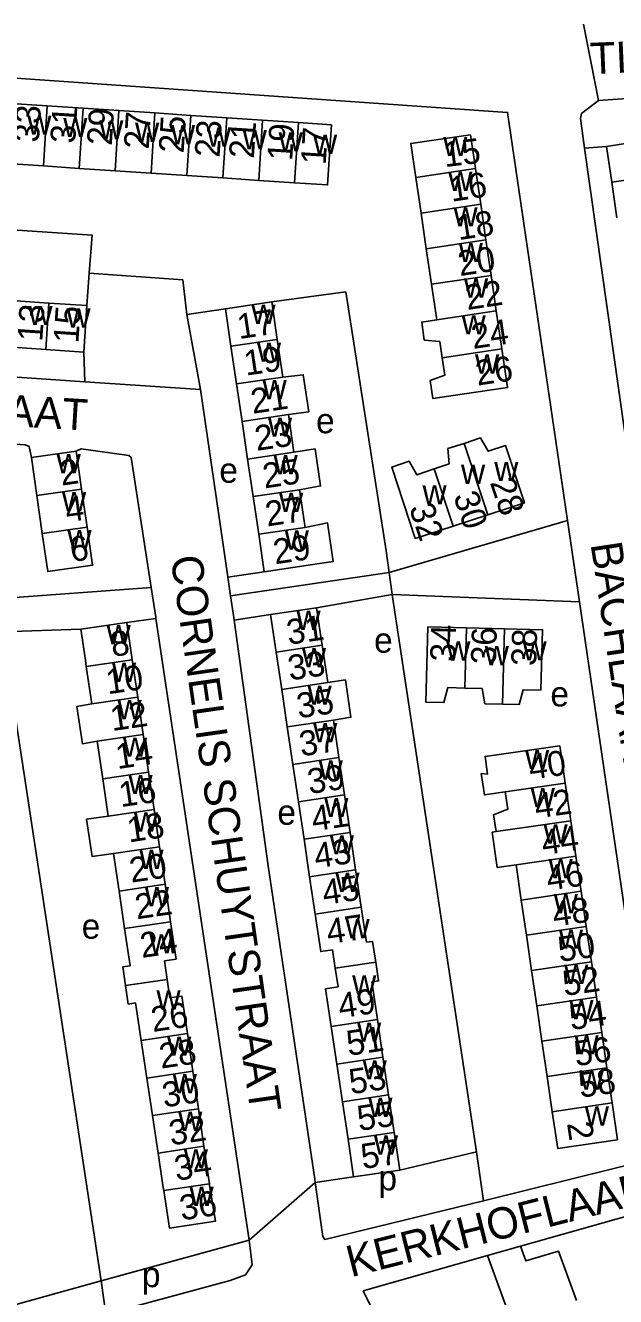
# Model space of a CAD drawing. Extents: x 159045 to 160918, y 380454 to 382516.
# Drawn here: x 159415.3 to 159509.6, y 380982.2 to 381185.5 of the extents above; entities that cross this region are included whole.
import ezdxf

# ---------------------------------------------------------------- set-up
doc = ezdxf.new("R2010")
doc.units = 0
for name, color, linetype in [('BLT_Basislijn', 7, 'Continuous'), ('BLT_Bebouwing', 7, 'Continuous'), ('BLT_Centroide', 7, 'Continuous'), ('BLT_Huisnummer', 7, 'Continuous'), ('BLT_Huisnummer_ tussenligend', 7, 'Continuous'), ('BLT_Onderverdeling_panden', 7, 'Continuous'), ('BLT_Straatnaam', 7, 'Continuous'), ('BLT_Vlakafsluiter', 7, 'Continuous')]:
    doc.layers.add(name, color=color, linetype=linetype)

msp = doc.modelspace()

# ---------------------------------------------------------------- linework, layer by layer
at = {"layer": 'BLT_Basislijn'}
for p, q in [((159504.65, 381165.85), (159508.16, 381166.12)), ((159504.65, 381165.85), (159511.98, 381113.94)), ((159424.57, 381133.23), (159424.74, 381128.49)), ((159424.74, 381128.49), (159443.24, 381127.24)), ((159501.91, 381106.29), (159473.38, 381098)), ((159501.91, 381106.29), (159503.82, 381093.29)), ((159447.6, 381097.25), (159453.42, 381098.11)), ((159447.6, 381097.25), (159448.04, 381094.26)), ((159473.38, 381098), (159448.04, 381094.26)), ((159473.88, 381094.5), (159473.38, 381098)), ((159406.83, 381093.49), (159435.36, 381095.58)), ((159461.81, 381092.35), (159473.88, 381094.5)), ((159473.88, 381094.5), (159503.82, 381093.29)), ((159448.61, 381090.35), (159454.45, 381091.26)), ((159436.12, 381090.64), (159431.45, 381090.01)), ((159451.01, 380991.23), (159436.12, 381090.64)), ((159424.11, 381088.94), (159411.57, 381088.52)), ((159411.57, 381088.52), (159427.34, 380984.74)), ((159475.09, 381002.45), (159487.38, 381005.39)), ((159487.38, 381005.39), (159488.5, 380997.53)), ((159467.71, 381001.35), (159461.58, 381000.46)), ((159494.38, 380990.27), (159515.4, 380996.22)), ((159427.34, 380984.74), (159451.01, 380991.23)), ((159489.14, 380988.79), (159494.38, 380990.27)), ((159469.22, 380983.16), (159489.14, 380988.79)), ((159493.11, 380977.83), (159489.14, 380988.79)), ((159427.34, 380984.74), (159401.24, 380977.5)), ((159428.12, 380979.39), (159427.34, 380984.74)), ((159471.52, 380978.46), (159469.22, 380983.16))]:
    msp.add_line(p, q, dxfattribs=at)
for points in [[(159372.56, 381179.9), (159492.32, 381171.55), (159501.91, 381106.29)], [(159506.86, 381173.46), (159546.37, 381176.21), (159549.81, 381173.28), (159549.76, 381169.23)], [(159504.65, 381165.85), (159504, 381170.58), (159504.16, 381171.37), (159506.86, 381173.46)], [(159425.46, 381145.86), (159425.92, 381151.93), (159383.62, 381154.73)], [(159425.07, 381140.66), (159425.46, 381145.86)], [(159441.06, 381139.22), (159440.41, 381144.8), (159425.46, 381145.86)], [(159454.64, 381141.26), (159466.45, 381142.84), (159472.9, 381101.45), (159473.38, 381098)], [(159441.06, 381139.22), (159447.22, 381140.16)], [(159443.24, 381127.24), (159441.06, 381139.22)], [(159365.96, 381132.51), (159399.9, 381130.18), (159424.74, 381128.49)], [(159443.24, 381127.24), (159447.54, 381097.66), (159447.6, 381097.25)], [(159416.22, 381116.38), (159415.86, 381118.12), (159415.22, 381118.39), (159403, 381119.22)], [(159423.38, 381117.4), (159424.16, 381117.76), (159431.78, 381116.69), (159432.16, 381116.4), (159435.36, 381095.58)], [(159435.36, 381095.58), (159436.08, 381090.87), (159436.12, 381090.64)], [(159448.04, 381094.26), (159448.55, 381090.78), (159448.61, 381090.35)], [(159473.88, 381094.5), (159487.28, 381006.08), (159487.38, 381005.39)], [(159503.82, 381093.29), (159516.85, 381004.58)], [(159461.58, 381000.46), (159461.5, 381000.99), (159454.07, 381051.07), (159448.61, 381090.35)], [(159516.85, 381004.58), (159488.5, 380997.53)], [(159461.58, 381000.46), (159462.77, 380991.85), (159463.09, 380991.37), (159488.5, 380997.53)], [(159451.01, 380991.23), (159451.52, 380987.33), (159450.46, 380985.71), (159447.97, 380984.78), (159428.12, 380979.39)], [(159494.38, 380990.27), (159495.25, 380987.93), (159500.46, 380989.49), (159503.36, 380981.6)]]:
    msp.add_lwpolyline(points, dxfattribs=at)
at = {"layer": 'BLT_Bebouwing'}
for p, q in [((159418.74, 381172.61), (159413, 381173)), ((159424.48, 381172.23), (159418.74, 381172.61)), ((159430.21, 381171.84), (159424.48, 381172.23)), ((159435.95, 381171.46), (159430.21, 381171.84)), ((159441.69, 381171.07), (159435.95, 381171.46)), ((159447.43, 381170.69), (159441.69, 381171.07)), ((159453.16, 381170.3), (159447.43, 381170.69)), ((159458.9, 381169.92), (159453.16, 381170.3)), ((159464.18, 381169.56), (159458.9, 381169.92)), ((159486.41, 381167.99), (159487.2, 381162.57)), ((159515.44, 381167.24), (159508.16, 381166.12)), ((159508.16, 381166.12), (159508.98, 381160.39)), ((159412.39, 381163.37), (159418.13, 381162.99)), ((159418.13, 381162.99), (159423.87, 381162.6)), ((159423.87, 381162.6), (159429.6, 381162.22)), ((159429.6, 381162.22), (159435.34, 381161.84)), ((159487.2, 381162.57), (159488.04, 381156.88)), ((159478.5, 381155.45), (159477.66, 381161.14)), ((159508.98, 381160.39), (159509.8, 381154.67)), ((159488.04, 381156.88), (159488.87, 381151.19)), ((159479.33, 381149.76), (159478.5, 381155.45)), ((159488.87, 381151.19), (159489.7, 381145.5)), ((159480.17, 381144.08), (159479.33, 381149.76)), ((159481, 381138.39), (159480.17, 381144.08)), ((159489.7, 381145.5), (159490.53, 381139.81)), ((159419.01, 381141.07), (159412.95, 381141.49)), ((159425.07, 381140.66), (159419.01, 381141.07)), ((159447.22, 381140.16), (159448.11, 381134.16)), ((159455.52, 381135.25), (159454.64, 381141.26)), ((159490.53, 381139.81), (159491.42, 381133.73)), ((159418.51, 381133.64), (159412.44, 381134.05)), ((159448.11, 381134.16), (159448.99, 381128.15)), ((159456.41, 381129.24), (159455.52, 381135.25)), ((159424.57, 381133.23), (159418.51, 381133.64)), ((159448.99, 381128.15), (159449.88, 381122.14)), ((159449.88, 381122.14), (159450.77, 381116.13)), ((159458.18, 381117.23), (159457.29, 381123.23)), ((159416.22, 381116.38), (159423.38, 381117.4)), ((159417.09, 381110.3), (159416.22, 381116.38)), ((159423.38, 381117.4), (159424.24, 381111.32)), ((159450.77, 381116.13), (159451.65, 381110.12)), ((159424.24, 381111.32), (159425.11, 381105.24)), ((159417.95, 381104.22), (159417.09, 381110.3)), ((159451.65, 381110.12), (159452.54, 381104.12)), ((159459.95, 381105.21), (159459.07, 381111.22)), ((159477.57, 381103.43), (159483.61, 381105.4)), ((159483.61, 381105.4), (159489.17, 381107.21)), ((159452.54, 381104.12), (159453.42, 381098.11)), ((159454.45, 381091.26), (159461.81, 381092.35)), ((159455.34, 381085.28), (159454.45, 381091.26)), ((159431.45, 381090.01), (159424.11, 381088.94)), ((159432.33, 381084.03), (159431.45, 381090.01)), ((159479.6, 381089.32), (159485.77, 381089.16)), ((159485.77, 381089.16), (159491.86, 381089)), ((159456.23, 381079.29), (159455.34, 381085.28)), ((159462.7, 381086.37), (159463.59, 381080.38)), ((159424.99, 381082.96), (159425.86, 381076.98)), ((159433.2, 381078.05), (159432.33, 381084.03)), ((159457.12, 381073.3), (159456.23, 381079.29)), ((159434.08, 381072.07), (159433.2, 381078.05)), ((159458.01, 381067.32), (159457.12, 381073.3)), ((159464.48, 381074.4), (159465.37, 381068.41)), ((159426.74, 381071), (159427.61, 381065.01)), ((159434.95, 381066.09), (159434.08, 381072.07)), ((159500.66, 381070.3), (159501.54, 381064.32)), ((159458.9, 381061.33), (159458.01, 381067.32)), ((159465.37, 381068.41), (159466.26, 381062.43)), ((159427.61, 381065.01), (159428.49, 381059.03)), ((159435.83, 381060.11), (159434.95, 381066.09)), ((159501.54, 381064.32), (159502.42, 381058.29)), ((159459.79, 381055.35), (159458.9, 381061.33)), ((159466.26, 381062.43), (159467.15, 381056.44)), ((159436.7, 381054.12), (159435.83, 381060.11)), ((159467.15, 381056.44), (159468.04, 381050.46)), ((159502.42, 381058.29), (159503.24, 381052.65)), ((159460.68, 381049.36), (159459.79, 381055.35)), ((159429.36, 381053.05), (159430.24, 381047.07)), ((159437.58, 381048.14), (159436.7, 381054.12)), ((159468.04, 381050.46), (159468.93, 381044.47)), ((159494.52, 381045.62), (159493.69, 381051.26)), ((159461.57, 381043.38), (159460.68, 381049.36)), ((159430.24, 381047.07), (159431.11, 381041.09)), ((159438.45, 381042.16), (159437.58, 381048.14)), ((159468.93, 381044.47), (159469.76, 381038.88)), ((159495.34, 381039.99), (159494.52, 381045.62)), ((159431.11, 381041.09), (159431.99, 381035.11)), ((159496.17, 381034.34), (159495.34, 381039.99)), ((159464.79, 381034.71), (159464.35, 381037.67)), ((159437.9, 381032.93), (159437.46, 381035.91)), ((159465.23, 381031.74), (159464.79, 381034.71)), ((159497, 381028.7), (159496.17, 381034.34)), ((159438.33, 381029.97), (159437.9, 381032.93)), ((159471.51, 381026.53), (159470.62, 381032.54)), ((159433.76, 381023.17), (159432.86, 381029.17)), ((159497.83, 381023.06), (159497, 381028.7)), ((159472.41, 381020.51), (159471.51, 381026.53)), ((159442.03, 381018.27), (159441.15, 381024.27)), ((159465.03, 381019.41), (159464.14, 381025.43)), ((159434.66, 381017.17), (159433.76, 381023.17)), ((159498.65, 381017.43), (159497.83, 381023.06)), ((159473.3, 381014.49), (159472.41, 381020.51)), ((159442.91, 381012.27), (159442.03, 381018.27)), ((159465.93, 381013.39), (159465.03, 381019.41)), ((159509.02, 381013.18), (159508.19, 381018.82)), ((159435.56, 381011.17), (159434.66, 381017.17)), ((159499.48, 381011.79), (159498.65, 381017.43)), ((159474.2, 381008.47), (159473.3, 381014.49)), ((159443.79, 381006.27), (159442.91, 381012.27)), ((159466.82, 381007.38), (159465.93, 381013.39)), ((159436.46, 381005.17), (159435.56, 381011.17)), ((159444.66, 381000.26), (159443.79, 381006.27)), ((159467.71, 381001.35), (159466.82, 381007.38)), ((159437.23, 381000.01), (159436.46, 381005.17)), ((159475.09, 381002.45), (159467.71, 381001.35)), ((159437.36, 380999.17), (159437.23, 381000.01)), ((159444.7, 381000), (159444.66, 381000.26))]:
    msp.add_line(p, q, dxfattribs=at)
for points in [[(159458.29, 381160.3), (159463.56, 381159.95), (159464.18, 381169.56)], [(159477.66, 381161.14), (159476.86, 381166.59), (159486.41, 381167.99)], [(159435.34, 381161.84), (159441.08, 381161.45)], [(159441.08, 381161.45), (159446.82, 381161.07)], [(159446.82, 381161.07), (159452.55, 381160.68)], [(159452.55, 381160.68), (159458.29, 381160.3)], [(159424.57, 381133.23), (159424.91, 381138.22), (159425.07, 381140.66)], [(159454.64, 381141.26), (159452.17, 381140.89), (159447.22, 381140.16)], [(159481.87, 381132.3), (159481.48, 381134.92), (159479.02, 381135.15), (159478.6, 381138.03), (159481, 381138.39)], [(159491.42, 381133.73), (159492.32, 381127.56), (159480.4, 381125.8), (159479.97, 381128.7), (159482.28, 381129.52), (159481.87, 381132.3)], [(159457.29, 381123.23), (159460.55, 381123.68), (159459.67, 381129.61), (159456.41, 381129.24)], [(159489.17, 381107.21), (159495.01, 381109.11), (159492.01, 381118.29), (159489.23, 381117.38), (159487.98, 381119.5), (159485.37, 381118.64)], [(159459.07, 381111.22), (159462.43, 381111.83), (159461.55, 381117.76), (159458.18, 381117.23)], [(159485.37, 381118.64), (159482.78, 381117.79), (159482.99, 381115.34), (159480.57, 381114.54)], [(159480.57, 381114.54), (159477.81, 381113.63), (159476.61, 381115.77), (159473.82, 381114.85), (159477.57, 381103.43)], [(159425.11, 381105.24), (159425.98, 381099.16), (159418.82, 381098.14), (159417.95, 381104.22)], [(159453.42, 381098.11), (159460.84, 381099.2), (159464.47, 381099.74), (159463.56, 381105.93), (159459.95, 381105.21)], [(159461.81, 381092.35), (159462.54, 381087.41), (159462.7, 381086.37)], [(159485.48, 381079.5), (159482.79, 381079.58), (159482.16, 381077.2), (159479.27, 381077.28), (159479.6, 381089.32)], [(159491.86, 381089), (159497.92, 381088.85), (159497.67, 381079.19), (159494.8, 381079.25), (159494.16, 381076.87), (159491.51, 381076.95)], [(159424.11, 381088.94), (159424.84, 381083.99), (159424.99, 381082.96)], [(159463.59, 381080.38), (159466.41, 381080.81), (159467.29, 381074.85), (159464.48, 381074.4)], [(159491.51, 381076.95), (159488.71, 381077.02), (159488.25, 381079.43), (159485.48, 381079.5)], [(159425.86, 381076.98), (159423.49, 381076.57), (159424.36, 381070.61), (159426.74, 381071)], [(159491.96, 381062.91), (159488.63, 381062.43), (159488.13, 381065.85), (159489.14, 381065.75), (159488.73, 381068.55), (159500.66, 381070.3)], [(159490.49, 381056.56), (159490.1, 381059.23), (159492.36, 381060.13), (159491.96, 381062.91)], [(159428.49, 381059.03), (159425.03, 381058.54), (159425.9, 381052.59), (159429.36, 381053.05)], [(159493.69, 381051.26), (159490.67, 381050.81), (159489.84, 381056.46), (159490.49, 381056.56)], [(159503.24, 381052.65), (159504.07, 381047.02)], [(159504.07, 381047.02), (159504.89, 381041.37)], [(159464.35, 381037.67), (159462.46, 381037.39), (159461.57, 381043.38)], [(159437.46, 381035.91), (159439.33, 381036.18), (159438.45, 381042.16)], [(159504.89, 381041.37), (159505.72, 381035.73)], [(159469.76, 381038.88), (159470.74, 381039.02), (159471.23, 381036.01), (159471.28, 381035.67)], [(159431.25, 381031.96), (159430.81, 381034.93), (159431.99, 381035.11)], [(159471.28, 381035.67), (159471.72, 381032.69), (159470.62, 381032.54)], [(159505.72, 381035.73), (159506.55, 381030.08)], [(159432.86, 381029.17), (159431.68, 381028.99), (159431.25, 381031.96)], [(159441.15, 381024.27), (159440.28, 381030.25), (159438.33, 381029.97)], [(159464.14, 381025.43), (159463.24, 381031.45), (159465.23, 381031.74)], [(159506.55, 381030.08), (159507.37, 381024.45)], [(159507.37, 381024.45), (159508.19, 381018.82)], [(159509.02, 381013.18), (159509.88, 381007.3), (159500.34, 381005.92), (159499.48, 381011.79)], [(159475.09, 381002.45), (159474.36, 381007.4), (159474.2, 381008.47)], [(159444.7, 381000), (159445.63, 380994.27), (159438.26, 380993.17), (159437.52, 380998.11), (159437.36, 380999.17)]]:
    msp.add_lwpolyline(points, dxfattribs=at)
at = {"layer": 'BLT_Onderverdeling_panden'}
for p, q in [((159418.13, 381162.99), (159418.74, 381172.61)), ((159423.87, 381162.6), (159424.48, 381172.23)), ((159429.6, 381162.22), (159430.21, 381171.84)), ((159435.34, 381161.84), (159435.95, 381171.46)), ((159441.08, 381161.45), (159441.69, 381171.07)), ((159446.82, 381161.07), (159447.43, 381170.69)), ((159452.55, 381160.68), (159453.16, 381170.3)), ((159458.29, 381160.3), (159458.9, 381169.92)), ((159477.66, 381161.14), (159487.2, 381162.57)), ((159508.98, 381160.39), (159516.25, 381161.43)), ((159478.5, 381155.45), (159488.04, 381156.88)), ((159479.33, 381149.76), (159488.87, 381151.19)), ((159480.17, 381144.08), (159489.7, 381145.5)), ((159418.51, 381133.64), (159419.01, 381141.07)), ((159481, 381138.39), (159490.53, 381139.81)), ((159448.11, 381134.16), (159455.52, 381135.25)), ((159481.87, 381132.3), (159491.42, 381133.73)), ((159448.99, 381128.15), (159456.41, 381129.24)), ((159449.88, 381122.14), (159457.29, 381123.23)), ((159489.17, 381107.21), (159485.37, 381118.64)), ((159450.77, 381116.13), (159458.18, 381117.23)), ((159483.61, 381105.4), (159480.57, 381114.54)), ((159424.24, 381111.32), (159417.09, 381110.3)), ((159451.65, 381110.12), (159459.07, 381111.22)), ((159425.11, 381105.24), (159417.95, 381104.22)), ((159452.54, 381104.12), (159459.95, 381105.21)), ((159485.48, 381079.5), (159485.77, 381089.16)), ((159491.51, 381076.95), (159491.86, 381089)), ((159455.34, 381085.28), (159462.7, 381086.37)), ((159432.33, 381084.03), (159424.99, 381082.96)), ((159456.23, 381079.29), (159463.59, 381080.38)), ((159433.2, 381078.05), (159425.86, 381076.98)), ((159457.12, 381073.3), (159464.48, 381074.4)), ((159434.08, 381072.07), (159426.74, 381071)), ((159458.01, 381067.32), (159465.37, 381068.41)), ((159434.95, 381066.09), (159427.61, 381065.01)), ((159491.96, 381062.91), (159501.54, 381064.32)), ((159458.9, 381061.33), (159466.26, 381062.43)), ((159435.83, 381060.11), (159428.49, 381059.03)), ((159459.79, 381055.35), (159467.15, 381056.44)), ((159490.49, 381056.56), (159502.42, 381058.29)), ((159436.7, 381054.12), (159429.36, 381053.05)), ((159493.69, 381051.26), (159503.24, 381052.65)), ((159460.68, 381049.36), (159468.04, 381050.46)), ((159437.58, 381048.14), (159430.24, 381047.07)), ((159494.52, 381045.62), (159504.07, 381047.02)), ((159461.57, 381043.38), (159468.93, 381044.47)), ((159438.45, 381042.16), (159431.11, 381041.09)), ((159495.34, 381039.99), (159504.89, 381041.37)), ((159464.79, 381034.71), (159471.28, 381035.67)), ((159496.17, 381034.34), (159505.72, 381035.73)), ((159431.25, 381031.96), (159437.9, 381032.93)), ((159497, 381028.7), (159506.55, 381030.08)), ((159464.14, 381025.43), (159471.51, 381026.53)), ((159433.76, 381023.17), (159441.15, 381024.27)), ((159497.83, 381023.06), (159507.37, 381024.45)), ((159465.03, 381019.41), (159472.41, 381020.51)), ((159434.66, 381017.17), (159442.03, 381018.27)), ((159498.65, 381017.43), (159508.19, 381018.82)), ((159465.93, 381013.39), (159473.3, 381014.49)), ((159435.56, 381011.17), (159442.91, 381012.27)), ((159499.48, 381011.79), (159509.02, 381013.18)), ((159466.82, 381007.38), (159474.2, 381008.47)), ((159436.46, 381005.17), (159443.79, 381006.27)), ((159437.36, 380999.17), (159444.66, 381000.26))]:
    msp.add_line(p, q, dxfattribs=at)
at = {"layer": 'BLT_Vlakafsluiter'}
for p, q in [((159506.86, 381173.46), (159504.47, 381185.66)), ((159461.58, 381000.46), (159451.01, 380991.23))]:
    msp.add_line(p, q, dxfattribs=at)

# ---------------------------------------------------------------- texts
at = {"layer": 'BLT_Centroide'}
for s, p in [('w', (159415.56, 381167.98)), ('w', (159421.3, 381167.61)), ('w', (159427.05, 381167.23)), ('w', (159432.78, 381166.83)), ('w', (159438.52, 381166.45)), ('w', (159444.25, 381166.08)), ('w', (159449.98, 381165.67)), ('w', (159455.73, 381165.3)), ('w', (159461.23, 381164.92)), ('w', (159482.03, 381164.56)), ('w', (159482.84, 381159)), ('w', (159483.68, 381153.31)), ('w', (159484.52, 381147.62)), ('w', (159485.35, 381141.94)), ('w', (159415.73, 381137.55)), ('w', (159421.8, 381137.14)), ('w', (159451.37, 381137.72)), ('w', (159484.98, 381136.06)), ('w', (159452.26, 381131.69)), ('w', (159487.12, 381129.78)), ('w', (159453.15, 381125.69)), ('w', (159454.02, 381119.69)), ('e', (159461.71, 381120.25)), ('w', (159420.23, 381113.84)), ('e', (159446.25, 381112.34)), ('w', (159454.91, 381113.69)), ('w', (159490.19, 381112.61)), ('w', (159484.88, 381112.14)), ('w', (159478.72, 381108.88)), ('w', (159421.1, 381107.78)), ('w', (159455.8, 381107.66)), ('w', (159421.96, 381101.69)), ('w', (159456.7, 381101.66)), ('w', (159458.57, 381088.81)), ('w', (159428.22, 381086.5)), ('e', (159470.99, 381085.17)), ('w', (159482.52, 381083.91)), ('w', (159494.72, 381083.94)), ('w', (159459.46, 381082.84)), ('w', (159488.67, 381083.16)), ('w', (159429.09, 381080.5)), ('w', (159460.35, 381076.84)), ('e', (159499.17, 381076.58)), ('w', (159429.97, 381074.53)), ('w', (159461.24, 381070.84)), ('w', (159430.84, 381068.53)), ('w', (159495.12, 381066.56)), ('w', (159462.13, 381064.88)), ('w', (159431.72, 381062.56)), ('w', (159496.02, 381060.44)), ('e', (159455.53, 381057.66)), ('w', (159463.02, 381058.88)), ('w', (159432.59, 381056.56)), ('w', (159498.07, 381054.66)), ('w', (159463.91, 381052.91)), ('w', (159433.47, 381050.59)), ('w', (159498.88, 381049.12)), ('w', (159464.8, 381046.91)), ('w', (159434.34, 381044.62)), ('w', (159499.7, 381043.5)), ('e', (159424.25, 381039.44)), ('w', (159466.42, 381039.52)), ('w', (159500.53, 381037.84)), ('w', (159435.06, 381037.09)), ('w', (159501.36, 381032.22)), ('w', (159467.48, 381030.52)), ('w', (159436.2, 381028.11)), ('w', (159502.19, 381026.56)), ('w', (159468.27, 381022.97)), ('w', (159503.02, 381020.94)), ('w', (159437.9, 381020.72)), ('w', (159469.16, 381016.94)), ('w', (159503.84, 381015.31)), ('w', (159438.79, 381014.72)), ('w', (159470.06, 381010.94)), ('w', (159439.67, 381008.72)), ('w', (159504.67, 381009.56)), ('w', (159470.96, 381004.91)), ('w', (159440.57, 381002.72)), ('p', (159471.68, 380999.21)), ('w', (159441.48, 380996.72)), ('p', (159433.87, 380983.73))]:
    msp.add_text(s, height=4, dxfattribs=at).set_placement(p)
at = {"layer": 'BLT_Huisnummer'}
for s, rotation, p in [('33', 86.3705, (159417.39, 381166.67)), ('29', 86.3696, (159429.06, 381166.18)), ('25', 86.3682, (159440.54, 381164.96)), ('21', 86.371, (159451.77, 381164.11)), ('17', 86.371, (159463.25, 381163.11)), ('15', 6.9932, (159482.3, 381162.79)), ('16', 8.4986, (159483.37, 381157.25)), ('20', 8.494, (159484.7, 381145.37)), ('15', 86.1242, (159423.71, 381134.56)), ('17', 8.458, (159449.4, 381135.3)), ('26', 8.4967, (159487.51, 381127.86)), ('21', 8.4603, (159451.57, 381123.35)), ('2', 8.1099, (159421.03, 381111.87)), ('25', 8.4561, (159453.47, 381111.42)), ('28', 288.4203, (159489.48, 381112.4)), ('32', 288.4182, (159476.54, 381108.35)), ('6', 8.1099, (159422.64, 381099.65)), ('29', 8.4592, (159455.16, 381099.29)), ('31', 8.4571, (159457.31, 381086.42)), ('34', 88.3228, (159483.94, 381083.69)), ('8', 8.3268, (159429.17, 381084.49)), ('38', 88.3226, (159496.89, 381083)), ('35', 8.4571, (159458.91, 381074.66)), ('12', 8.3202, (159429.11, 381072.63)), ('40', 8.18, (159495.99, 381064.85)), ('39', 8.4625, (159460.63, 381062.56)), ('16', 8.3268, (159430.49, 381060.47)), ('44', 8.181, (159498.04, 381052.8)), ('43', 8.4561, (159461.7, 381050.68)), ('20', 8.3268, (159432.17, 381048.39)), ('48', 8.1753, (159499.8, 381041.36)), ('47', 8.4592, (159463.68, 381038.56)), ('24', 8.3217, (159433.86, 381036.36)), ('52', 8.1763, (159501.41, 381030.28)), ('49', 8.4571, (159465.56, 381026.71)), ('26', 8.5247, (159435.62, 381024.52)), ('53', 8.4571, (159467.28, 381014.56)), ('58', 8.1782, (159503.95, 381014.01)), ('30', 8.5292, (159437.41, 381012.45)), ('2', 278.3445, (159501.82, 381009.93)), ('57', 8.456, (159469.18, 381002.61)), ('36', 8.5387, (159440.21, 380994.39))]:
    msp.add_text(s, height=4, rotation=rotation, dxfattribs=at).set_placement(p)
at = {"layer": 'BLT_Huisnummer_ tussenligend'}
for s, rotation, p in [('31', 86.3696, (159423.19, 381166.51)), ('27', 86.3682, (159434.96, 381165.59)), ('23', 86.371, (159446.28, 381164.28)), ('19', 86.371, (159457.89, 381163.73)), ('18', 8.4986, (159484.49, 381151.12)), ('22', 8.494, (159485.88, 381139.95)), ('13', 86.123, (159417.94, 381134.83)), ('24', 8.494, (159486.82, 381133.72)), ('19', 8.458, (159450.49, 381129.45)), ('23', 8.4603, (159452.21, 381117.43)), ('4', 8.1099, (159421.89, 381106)), ('27', 8.4561, (159453.89, 381105.34)), ('30', 288.4203, (159483.62, 381110.23)), ('36', 88.3228, (159490.45, 381083.26)), ('33', 8.4571, (159457.51, 381080.72)), ('10', 8.3268, (159428.42, 381078.51)), ('37', 8.4571, (159459.33, 381068.58)), ('14', 8.3202, (159429.96, 381066.55)), ('42', 8.18, (159496.91, 381058.64)), ('41', 8.4561, (159461.28, 381056.61)), ('18', 8.3268, (159431.8, 381054.83)), ('46', 8.181, (159498.82, 381047.12)), ('45', 8.4561, (159463.01, 381044.82)), ('22', 8.3268, (159433.05, 381042.54)), ('50', 8.1753, (159500.66, 381035.72)), ('54', 8.1763, (159502.47, 381024.83)), ('51', 8.4571, (159466.87, 381020.7)), ('28', 8.5247, (159436.93, 381018.66)), ('56', 8.1763, (159503.24, 381019.05)), ('55', 8.4571, (159468.58, 381008.7)), ('32', 8.5292, (159438.51, 381006.38)), ('34', 8.5292, (159439.37, 381000.73))]:
    msp.add_text(s, height=4, rotation=rotation, dxfattribs=at).set_placement(p)
at = {"layer": 'BLT_Straatnaam'}
for s, height, rotation, p in [('TINELSTRAAT', 5, 2.4489, (159505.61, 381177.67)), ('CORNELIS SCHUYTSTRAAT', 4.9999, 356.6109, (159335.34, 381125.99)), ('BACHLAAN', 5, 278.6045, (159505.58, 381102.55)), ('CORNELIS SCHUYTSTRAAT', 4.9999, 278.1833, (159438.45, 381100.42)), ('KERKHOFLAAN', 5, 14.208, (159467.29, 380985.3))]:
    msp.add_text(s, height=height, rotation=rotation, dxfattribs=at).set_placement(p)

doc.saveas('drawing.dxf')
